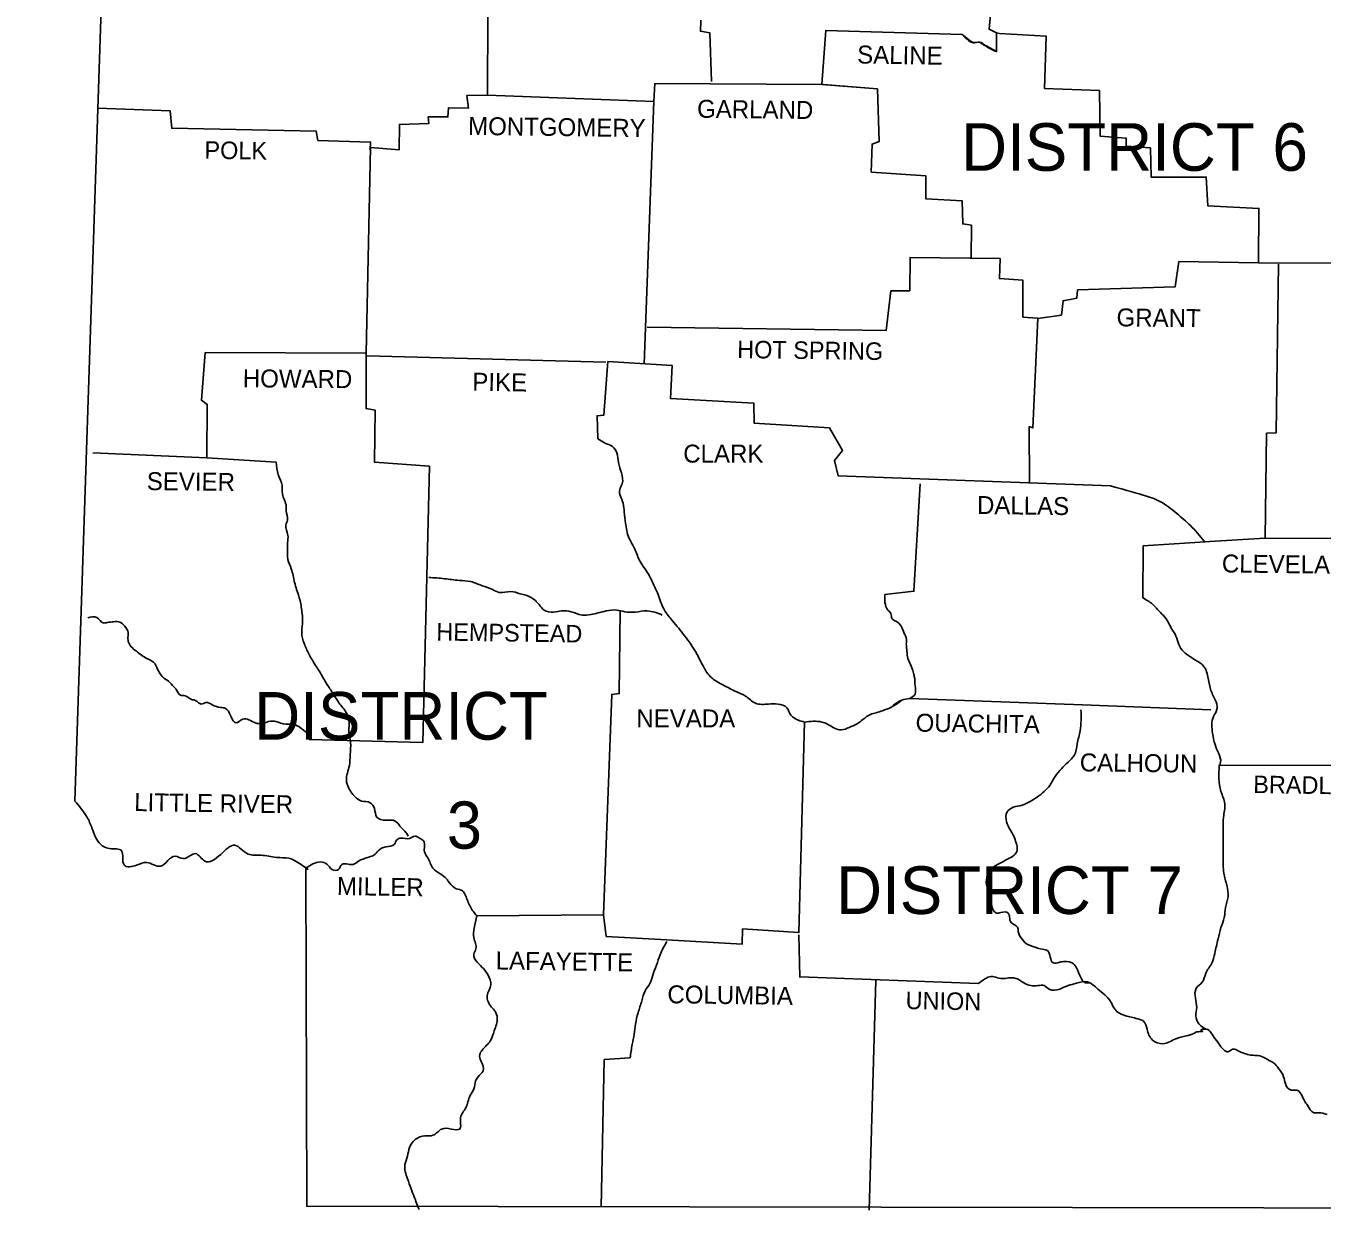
# Model space of a CAD drawing. Extents: x -33639 to 34530, y -17264 to 5867.
# Drawn here: x -17668 to -15961, y 2895 to 4454 of the extents above; entities that cross this region are included whole.
import ezdxf

# ---------------------------------------------------------------- set-up
doc = ezdxf.new("R2010")
doc.units = 0
for name, color, linetype in [('1', 7, 'Continuous'), ('2', 7, 'Continuous'), ('3', 7, 'Continuous'), ('S_MISC_BOUNDARY', 7, 'Continuous')]:
    doc.layers.add(name, color=color, linetype=linetype)

msp = doc.modelspace()

# ---------------------------------------------------------------- linework, layer by layer
at = {"layer": '1'}
for points in [[(-17667.8, 5841.4), (-17553.9, 4926.7), (-17603.4, 3433.6)], [(-17058.6, 4685.1), (-17059.7, 4363.2), (-17087.2, 4362.6), (-17085, 4346.1), (-17111.4, 4346.7), (-17111.9, 4334.6), (-17137.8, 4334.6), (-17137.3, 4325.8), (-17175.8, 4324.7), (-17176.3, 4291.1), (-17213.8, 4294.4), (-17219.8, 4023.6), (-17431.7, 4024.2), (-17436.7, 3961.4), (-17428.9, 3955.9), (-17429.5, 3885.5), (-17579.7, 3892.1)], [(-16215.4, 4527.2), (-16255, 4531.6), (-16253.4, 4516.7), (-16325.5, 4514), (-16327.7, 4492.5), (-16395.4, 4488.7), (-16399.2, 4450.1), (-16389.3, 4445.2), (-16389.3, 4420.6)], [(-16779, 4462.2), (-16779.5, 4447.4), (-16766.9, 4445.2), (-16764.7, 4381.3)], [(-16434.5, 4443), (-16614.4, 4448.5), (-16619.4, 4377.5), (-16839.5, 4378.6), (-16840.6, 4354.9)], [(-16385.5, 4444.6), (-16323.8, 4440.8), (-16326, 4372), (-16253.9, 4369.2), (-16252.8, 4309.2), (-16218.7, 4306.5), (-16218.7, 4296), (-16186.8, 4293.8), (-16185.7, 4255.3), (-16113.1, 4255.3), (-16110.9, 4217.3), (-16043.7, 4214), (-16044.3, 4142.5)], [(-16617.9, 4377.4), (-16546.2, 4371.4), (-16544, 4302.1), (-16553.3, 4298.8), (-16554.4, 4261.9), (-16482.3, 4257), (-16482.3, 4226.7), (-16434.5, 4223.9), (-16433.9, 4193.7), (-16422.4, 4192), (-16422.9, 4148.5)], [(-16840.6, 4354.9), (-17059.7, 4363.2)], [(-16840.6, 4354.9), (-16853.4, 4009.5)], [(-17573.1, 4346.1), (-17477.9, 4342.8), (-17475.7, 4319.7), (-17285.3, 4315.8), (-17283.1, 4303.7), (-17213.8, 4301.5), (-17214.3, 4291.1)], [(-15387.7, 4205.8), (-15595.7, 4211.3), (-15596.8, 4143.6), (-16017.8, 4141.9)], [(-16849.4, 4057.7), (-16534.6, 4053.3), (-16528.6, 4105.6), (-16503.8, 4105.6), (-16503.3, 4149.6), (-16384.4, 4148), (-16385.5, 4121.6), (-16354.7, 4119.4), (-16354.7, 4070.9), (-16336, 4069.4)], [(-16334.8, 4069.3), (-16304, 4073.7), (-16301.8, 4092.4), (-16283.7, 4095.7), (-16282.6, 4106.7), (-16154.3, 4110.6), (-16149.4, 4144.1), (-16017.8, 4141.9)], [(-16017.8, 4140.8), (-16021.1, 3918.5), (-16033.8, 3917.9), (-16035.5, 3779.8)], [(-16334.8, 4069.3), (-16341.4, 3925.1), (-16346.4, 3926.7), (-16345.9, 3851.9)], [(-17219.8, 4023.6), (-17219.8, 3950.4), (-17207.7, 3948.2), (-17208.8, 3880), (-17136.2, 3874.5), (-17145, 3510.7), (-17294.7, 3514.5)], [(-17218.7, 4019.8), (-16903.9, 4011.5)], [(-16914.4, 3910.8), (-16915.5, 3941.1), (-16906.7, 3941.6), (-16901.2, 4012.6), (-16816.4, 4007.1), (-16818.6, 3963.6), (-16709.1, 3957.6), (-16708.5, 3931.2), (-16609.5, 3925.1), (-16592.4, 3895.4), (-16602.9, 3882.2), (-16597.9, 3861.8), (-16239.1, 3848.6)], [(-17429.5, 3885.5), (-17338.1, 3880)], [(-16490, 3851.4), (-16498.3, 3709.9), (-16536.3, 3705.5)], [(-16114.7, 3774.9), (-16196.2, 3769.9), (-16196.7, 3701.1)], [(-16035.5, 3779.8), (-16115.8, 3774.9)], [(-16035.5, 3779.8), (-15840.6, 3778.7)], [(-16885.2, 3684.6), (-16886.3, 3575.1), (-16896.2, 3574), (-16907.2, 3283.9)], [(-16503.8, 3568.5), (-16276, 3560.2), (-16107, 3553.6)], [(-16642.5, 3537.6), (-16649.6, 3260.3), (-16723.9, 3265.2), (-16724.5, 3244.9), (-16823.6, 3250.9)], [(-16096, 3480.4), (-15847.2, 3481)], [(-17299.1, 3345), (-17298, 2899.8), (-15280.9, 2896.5)], [(-16823.6, 3250.9), (-16903.4, 3255.3), (-16907.2, 3283.9), (-17074, 3282.3)], [(-16413.5, 3193.1), (-16648.5, 3201.9), (-16649.6, 3257.5)], [(-16548.4, 3197), (-16557.2, 2894.8)], [(-16872, 3095.2), (-16906.1, 3093), (-16910, 2899.2)]]:
    msp.add_lwpolyline(points, dxfattribs=at)
for points in [[(-16389.3, 4420.6), (-16403.6, 4428.1), (-16411.9, 4433.1), (-16420.7, 4432.5), (-16427.9, 4436.9), (-16434.5, 4443)], [(-16914.4, 3910.8), (-16905.6, 3905.3), (-16895.1, 3900.3), (-16889.6, 3892.1), (-16887.4, 3879.4), (-16883.5, 3865.7), (-16882.4, 3851.4), (-16885.7, 3843.6), (-16881.3, 3826), (-16879.7, 3813.9), (-16878, 3799.6), (-16873.6, 3780.4), (-16866.5, 3767.1), (-16859.9, 3751.2), (-16848.9, 3734.1), (-16839.5, 3715.4), (-16835.1, 3705.5), (-16826.9, 3685.1), (-16816.4, 3671.4), (-16799.9, 3650.5), (-16785, 3629), (-16776.8, 3613), (-16764.1, 3595.4), (-16749.8, 3586.6), (-16731.6, 3577.3), (-16720.1, 3571.8), (-16706.9, 3562.4), (-16689.8, 3561.3), (-16677.2, 3561.3), (-16665.6, 3556.4), (-16660.1, 3546.5), (-16650.2, 3539.9), (-16642.5, 3537.6)], [(-17338.1, 3880), (-17335.4, 3863.5), (-17330.4, 3849.1), (-17329.9, 3838.1), (-17324.9, 3821.6), (-17324.9, 3815.6), (-17323.3, 3803.5), (-17325.5, 3796.9), (-17322.7, 3783.7), (-17323.3, 3773.8), (-17323.3, 3765.5), (-17322.7, 3751.7), (-17318.3, 3739.6), (-17313.9, 3721.5), (-17311.2, 3712.1), (-17306.8, 3697.8), (-17304, 3680.2), (-17303.5, 3667), (-17304.6, 3654.9), (-17301.3, 3641.1), (-17295.2, 3627.4), (-17287.5, 3614.1), (-17278.2, 3599.3), (-17271.5, 3587.7), (-17263.3, 3575.1), (-17256.7, 3564.6), (-17246.8, 3551.4), (-17242.4, 3540.4), (-17242.4, 3525), (-17240.2, 3510.7), (-17240.7, 3494.7), (-17241.8, 3480.4), (-17245.7, 3460.6), (-17242.9, 3451.2), (-17232.5, 3437.5), (-17225.9, 3433.6), (-17214.3, 3431.4), (-17208.8, 3423.7), (-17205.5, 3412.2), (-17193.9, 3408.3), (-17181.3, 3407.2), (-17175.2, 3400.6), (-17167, 3391.8), (-17164.2, 3387.4)], [(-16239.1, 3848.6), (-16196.2, 3836.5), (-16174.1, 3828.2), (-16152.1, 3812.3), (-16134, 3796.3), (-16115.8, 3776)], [(-17137.3, 3728.1), (-17116.3, 3726.4), (-17097.1, 3724.2), (-17082.2, 3722.6), (-17066.8, 3717.1), (-17053.1, 3712.1), (-17044.3, 3708.3), (-17029.4, 3709.4), (-17016.7, 3706.6), (-17002.4, 3701.7), (-16992, 3692.3), (-16985.4, 3685.1), (-16972.7, 3682.4), (-16962.2, 3684), (-16949.6, 3682.9), (-16935.3, 3678.5), (-16923.7, 3679.1), (-16914.4, 3681.3), (-16903.4, 3684), (-16889.6, 3685.1), (-16879.1, 3682.9), (-16865.4, 3682.4), (-16849.4, 3684), (-16829.6, 3678.5)], [(-16536.3, 3705.5), (-16536.3, 3695), (-16532.4, 3685.1), (-16528.6, 3680.7), (-16526.9, 3673.6), (-16522, 3670.3), (-16514.8, 3663.7), (-16511, 3654.3), (-16508.2, 3648.3), (-16508.2, 3640.6), (-16507.7, 3632.9), (-16506.6, 3623.5), (-16500, 3607), (-16498.3, 3600.4), (-16497.2, 3594.9), (-16496.6, 3585.5), (-16496.6, 3574.5), (-16503.8, 3568.5)], [(-16196.7, 3701.1), (-16184, 3692.8), (-16173.6, 3681.8), (-16165.9, 3673.6), (-16160.9, 3664.2), (-16154.3, 3653.2), (-16145, 3632.3), (-16136.7, 3625.2), (-16125.2, 3618), (-16118, 3613), (-16110.9, 3597.1), (-16107.5, 3581.1), (-16101.5, 3566.8), (-16098.7, 3555.8), (-16103.7, 3544.8), (-16104.8, 3522.8), (-16101.5, 3507.9), (-16097.1, 3496.9), (-16094.3, 3484.3), (-16096, 3480.4)], [(-17586.3, 3674.7), (-17574.2, 3675.2), (-17566, 3668.1), (-17561, 3668.6), (-17552.2, 3669.7), (-17544, 3669.2), (-17537.9, 3664.2), (-17533, 3655.4), (-17533.5, 3647.2), (-17533, 3643.9), (-17529.1, 3636.7), (-17522.5, 3631.2), (-17515.4, 3625.7), (-17508.7, 3621.3), (-17497.7, 3614.1), (-17496.6, 3611.9), (-17492.2, 3603.1), (-17486.7, 3596), (-17480.1, 3591.6), (-17473, 3583.9), (-17469.7, 3580.6), (-17464.2, 3572.9), (-17458.1, 3572.3), (-17449.9, 3567.4), (-17443.8, 3565.7), (-17437.2, 3561.3), (-17430.6, 3563.5), (-17422.3, 3560.2), (-17411.3, 3556.9), (-17405.3, 3555.8), (-17398.1, 3545.4), (-17391, 3536.5), (-17382.2, 3541.5), (-17365.7, 3536.5), (-17355.2, 3536), (-17345.8, 3538.7), (-17338.7, 3538.2), (-17325.5, 3534.9), (-17317.2, 3534.9), (-17308.4, 3531.6), (-17300.2, 3525), (-17294.7, 3517.8), (-17294.7, 3514.5)], [(-16528.6, 3556.9), (-16514.3, 3566.3), (-16503.8, 3568.5)], [(-16514.3, 3566.3), (-16528.6, 3556.9), (-16539.6, 3552.5), (-16547.8, 3549.8), (-16555.5, 3547.6), (-16565.4, 3541), (-16573.1, 3535.4), (-16583.6, 3530.5), (-16593.5, 3527.2), (-16605.6, 3531), (-16612.2, 3534.9), (-16619.4, 3537.6), (-16642.5, 3537.6)], [(-16278.2, 3553.6), (-16279.3, 3526.1), (-16283.1, 3509), (-16287, 3493.6), (-16295.2, 3484.8), (-16304, 3476), (-16312.3, 3466.1), (-16319.4, 3454), (-16326.6, 3446.3), (-16335.9, 3438.6), (-16345.3, 3433.1), (-16355.8, 3428.1), (-16367.3, 3425.4), (-16375.6, 3419.3), (-16376.1, 3406.1), (-16366.8, 3387.4), (-16363.5, 3378.6), (-16362.4, 3368.1), (-16366.2, 3362.1), (-16375, 3357.1), (-16385.5, 3351.1), (-16394.8, 3345.6), (-16401.4, 3336.2), (-16402.5, 3323.6), (-16398.1, 3308.7), (-16396.5, 3299.9), (-16389.3, 3286.1), (-16383.8, 3286.7), (-16373.9, 3286.1), (-16372.8, 3283.4), (-16372.3, 3280.6), (-16370.1, 3273.5), (-16361.8, 3267.4), (-16360.7, 3261.9), (-16355.8, 3251.5), (-16347.5, 3244.3), (-16341.4, 3242.1), (-16328.8, 3238.3), (-16322.2, 3236.6), (-16315, 3220.6), (-16306.2, 3221.2), (-16299.6, 3222.3), (-16288.6, 3219.5), (-16283.7, 3212.9), (-16278.7, 3201.9), (-16272.1, 3194.2), (-16267.7, 3194.2)], [(-16096, 3480.4), (-16093.8, 3446.3), (-16088.8, 3429.8), (-16090.5, 3412.2), (-16091, 3395.1), (-16091, 3379.7), (-16091, 3364.8), (-16091, 3349.4), (-16089.9, 3338.4), (-16086.1, 3322.5), (-16084.4, 3307.6), (-16087.7, 3293.3), (-16089.4, 3280.1), (-16093.8, 3266.9), (-16097.6, 3252), (-16102, 3232.8), (-16105.9, 3220.1), (-16113.6, 3206.9), (-16118.6, 3194.8), (-16126.3, 3187.1), (-16127.4, 3173.9), (-16125.7, 3161.8), (-16126.8, 3150.7), (-16123, 3140.3), (-16113.1, 3133.1)], [(-17603.4, 3433.6), (-17587.5, 3412.7), (-17580.8, 3397.9), (-17571.5, 3378.6), (-17557.7, 3370.9), (-17541.8, 3368.1), (-17538.5, 3349.4), (-17522, 3348.9), (-17508.7, 3352.7), (-17490.6, 3347.8), (-17471.3, 3361), (-17460.3, 3357.7), (-17444.4, 3364.3), (-17432.3, 3354.4), (-17411.3, 3363.2), (-17392.6, 3375.3), (-17375, 3363.7), (-17358, 3362.1), (-17337.6, 3359.3), (-17321.6, 3358.2), (-17307.3, 3351.1), (-17296.9, 3343.9), (-17299.1, 3345)], [(-17299.1, 3345), (-17279.8, 3353.3), (-17271.5, 3350.5), (-17264.4, 3343.4), (-17256.1, 3343.4), (-17251.7, 3350), (-17243.5, 3350.5), (-17236.9, 3350), (-17229.7, 3354.4), (-17223.7, 3357.1), (-17215.4, 3359.9), (-17209.4, 3362.1), (-17203.9, 3368.1), (-17193.9, 3373.1), (-17182.4, 3376.9), (-17179.1, 3382.4), (-17173.6, 3384.7), (-17162.6, 3384.1), (-17155.4, 3387.4), (-17149.4, 3384.7), (-17143.9, 3380.8), (-17142.8, 3366.5), (-17138.4, 3358.8), (-17131.8, 3345), (-17122.4, 3337.9), (-17113.6, 3330.7), (-17110.3, 3326.3), (-17100.9, 3318.1), (-17092.7, 3315.3), (-17088.8, 3309.3), (-17082.8, 3294.9), (-17074, 3282.3)], [(-17074, 3282.3), (-17077.3, 3266.3), (-17077.8, 3253.7), (-17075.1, 3238.8), (-17077.8, 3231.7), (-17073.4, 3221.2), (-17065.2, 3212.9), (-17059.1, 3204.1), (-17055.3, 3191.5), (-17060.2, 3177.2), (-17054.7, 3162.3), (-17049.8, 3156.8), (-17047, 3148), (-17050.9, 3130.9), (-17055.8, 3118.3), (-17066.8, 3105.6), (-17070.1, 3099.6), (-17068.5, 3091.3), (-17065.7, 3078.1), (-17068.5, 3074.3), (-17075.6, 3064.9), (-17077.8, 3054.4), (-17082.8, 3045.6), (-17088.3, 3029.7), (-17095.4, 3016.5), (-17096.5, 3001.6), (-17107.5, 3001.6), (-17120.2, 3001.6), (-17131.8, 2993.3), (-17142.2, 2992.8), (-17154.9, 2987.8), (-17162.6, 2977.4), (-17165.3, 2965.8), (-17168.6, 2954.8), (-17165.3, 2936.1), (-17160.4, 2922.9), (-17156.5, 2912.4), (-17149.9, 2895.4)], [(-16872, 3095.2), (-16869.2, 3112.8), (-16866.5, 3126.5), (-16864.8, 3139.7), (-16861.5, 3154.6), (-16856.6, 3170.6), (-16852.2, 3183.8), (-16846.1, 3193.1), (-16842.3, 3204.1), (-16837.3, 3217.3), (-16832.4, 3231.1), (-16823.6, 3248.7)], [(-16413.5, 3193.1), (-16404.7, 3199.2), (-16396.5, 3202.5), (-16388.2, 3200.8), (-16379.4, 3199.7), (-16371.7, 3200.8), (-16361.8, 3199.2), (-16353.6, 3194.2), (-16344.2, 3190.4), (-16334.8, 3190.4), (-16326.6, 3190.4), (-16319.4, 3185.4), (-16306.2, 3186), (-16295.2, 3190.4), (-16284.2, 3193.7), (-16269.4, 3195.3), (-16256.1, 3186), (-16246.8, 3178.3), (-16239.1, 3169.5), (-16233.6, 3159.6), (-16227.5, 3154.1), (-16217.6, 3150.2), (-16209.9, 3148.5), (-16200.6, 3145.8), (-16195.6, 3143.6), (-16191.2, 3133.1), (-16184, 3118.8), (-16170.3, 3113.9), (-16153.2, 3120.5), (-16139.5, 3124.3), (-16129.6, 3127.6), (-16123.5, 3129.8), (-16118, 3130.4), (-16119.7, 3131.5), (-16113.1, 3133.1), (-16107, 3128.7), (-16103.1, 3122.7), (-16096.5, 3113.9), (-16090.5, 3106.2), (-16084.4, 3103.4), (-16078.4, 3106.7), (-16070.1, 3104), (-16063, 3101.2), (-16054.7, 3099), (-16047.6, 3098.5), (-16038.2, 3096.3), (-16031, 3092.4), (-16024.4, 3088.6), (-16017.8, 3081.4), (-16011.2, 3070.4), (-16009, 3061.6), (-16001.3, 3052.8), (-15994.2, 3052.8), (-15983.7, 3038.5), (-15979.9, 3033), (-15971.6, 3023.1), (-15965.6, 3023.1), (-15954, 3020.9)]]:
    msp.add_spline(points, degree=3, dxfattribs=at)
at = {"layer": 'S_MISC_BOUNDARY'}
for p, q in [((-16614.4, 4448.5), (-16619.4, 4377.5)), ((-16434.5, 4443), (-16614.4, 4448.5)), ((-16389.3, 4445.2), (-16389.3, 4420.6)), ((-16326, 4372), (-16323.8, 4440.8)), ((-16389.3, 4420.6), (-16394.3, 4423.4)), ((-16619.4, 4377.5), (-16617.9, 4377.4)), ((-16617.9, 4377.4), (-16546.2, 4371.4)), ((-16253.9, 4369.2), (-16326, 4372)), ((-16186.8, 4293.8), (-16218.7, 4296)), ((-16482.3, 4226.7), (-16434.5, 4223.9)), ((-16434.5, 4223.9), (-16433.9, 4193.7)), ((-16304, 4073.7), (-16301.8, 4092.4)), ((-16301.8, 4092.4), (-16283.7, 4095.7)), ((-16354.7, 4070.9), (-16336, 4069.4)), ((-16336, 4069.4), (-16334.8, 4069.3)), ((-16334.8, 4069.3), (-16304, 4073.7))]:
    msp.add_line(p, q, dxfattribs=at)
for points in [[(-16619.4, 4377.5), (-16614.4, 4448.5), (-16434.5, 4443), (-16424.3, 4434.7), (-16420.7, 4432.5), (-16416.3, 4432.8), (-16411.9, 4433.1), (-16389.3, 4420.6), (-16389.3, 4445.2), (-16385.5, 4444.6), (-16323.8, 4440.8), (-16326, 4372), (-16253.9, 4369.2), (-16253.4, 4339.2), (-16252.8, 4309.2), (-16218.6, 4306.5), (-16218.8, 4296), (-16186.7, 4293.8), (-16185.7, 4255.3), (-16113.1, 4255.3), (-16110.9, 4217.3), (-16043.7, 4214), (-16044.3, 4142.5), (-16149.4, 4144.1), (-16154.3, 4110.6), (-16282.6, 4106.7), (-16283.7, 4095.7), (-16301.8, 4092.4), (-16304, 4073.7), (-16334.8, 4069.3), (-16336, 4069.4), (-16354.7, 4070.9), (-16354.7, 4119.4), (-16385.5, 4121.6), (-16384.4, 4148), (-16422.9, 4148.5), (-16422.4, 4192), (-16433.9, 4193.7), (-16434.5, 4223.9), (-16482.3, 4226.7), (-16482.3, 4257), (-16554.4, 4261.9), (-16553.3, 4298.8), (-16544, 4302.1), (-16546.2, 4371.4), (-16619.4, 4377.5)], [(-16323.8, 4440.8), (-16385.5, 4444.6), (-16389.3, 4445.2)], [(-16411, 4432.6), (-16411.9, 4433.1), (-16416.3, 4432.8), (-16416.6, 4432.8)], [(-16546.2, 4371.4), (-16544, 4302.1), (-16553.3, 4298.8), (-16554.4, 4261.9)], [(-16218.7, 4296), (-16218.7, 4306.5), (-16252.8, 4309.2), (-16253.4, 4339.2), (-16253.9, 4369.2)], [(-16113.1, 4255.3), (-16185.7, 4255.3), (-16186.8, 4293.8)], [(-16554.4, 4261.9), (-16482.3, 4257), (-16482.3, 4226.7)], [(-16283.7, 4095.7), (-16282.6, 4106.7), (-16154.3, 4110.6), (-16149.4, 4144.1), (-16044.3, 4142.5), (-16043.7, 4214), (-16110.9, 4217.3), (-16113.1, 4255.3)], [(-16433.9, 4193.7), (-16422.4, 4192), (-16422.9, 4148.5)], [(-16422.9, 4148.5), (-16384.4, 4148), (-16385.5, 4121.6)], [(-16385.5, 4121.6), (-16354.7, 4119.4), (-16354.7, 4070.9)]]:
    msp.add_lwpolyline(points, dxfattribs=at)
msp.add_open_spline([(-16416.6, 4432.8), (-16418, 4432.4), (-16419.4, 4432), (-16420.7, 4432.5), (-16423.3, 4433.6), (-16425.7, 4435.1), (-16427.9, 4436.9), (-16430.2, 4438.9), (-16432.4, 4440.8), (-16434.5, 4443)], degree=3, dxfattribs=at)
msp.add_spline([(-16394.3, 4423.4), (-16399, 4425.7), (-16403.6, 4428.1), (-16404.6, 4428.6), (-16405.5, 4429.2), (-16407.3, 4430.3), (-16409.1, 4431.5), (-16411, 4432.6)], degree=3, dxfattribs=at)

# ---------------------------------------------------------------- texts
at = {"layer": '2'}
for s, height, rotation, p in [('SALINE', 23.67, 359.1491, (-16573.1, 4405)), ('GARLAND', 23.67, 359.3658, (-16783.9, 4333.5)), ('MONTGOMERY', 23.67, 359.2944, (-17085.5, 4310.9)), ('POLK', 23.11, 359.2152, (-17432.8, 4279.5)), ('GRANT', 23.67, 359.4032, (-16231.4, 4058.8)), ('HOT SPRING', 23.11, 359.2216, (-16731.1, 4017)), ('HOWARD', 23.67, 359.5145, (-17382.2, 3978.5)), ('PIKE', 23.66, 359.0452, (-17080, 3974.1)), ('SEVIER', 23.67, 359.4271, (-17508.7, 3843.1)), ('DALLAS', 23.66, 359.2462, (-16415.2, 3811.7)), ('CLEVELAND', 23.67, 359.3377, (-16092.7, 3734.7)), ('HEMPSTEAD', 23.11, 359.1885, (-17127.4, 3645)), ('OUACHITA', 23.67, 359.2043, (-16496.1, 3525)), ('CALHOUN', 23.67, 359.3634, (-16279.8, 3472.7)), ('BRADLEY', 23.11, 359.1449, (-16051.4, 3444.1)), ('LITTLE RIVER', 23.666, 359.1697, (-17525.3, 3420.4)), ('MILLER', 23.66, 359.1319, (-17258.3, 3309.8)), ('LAFAYETTE', 23.66, 359.1839, (-17049.2, 3211.8)), ('COLUMBIA', 23.66, 359.2125, (-16823, 3167.3)), ('UNION', 23.11, 358.9584, (-16509.3, 3159.6))]:
    msp.add_text(s, height=height, rotation=rotation, dxfattribs=at).set_placement(p)
for s, p in [('CLARK', (-16802, 3879.3)), ('NEVADA', (-16863.7, 3530.5))]:
    msp.add_text(s, height=23.67, dxfattribs=at).set_placement(p)
at = {"layer": '3'}
for s, height, p in [('DISTRICT 6', 62.74, (-16436.1, 4263.6)), ('DISTRICT', 62.74, (-17367.1, 3514.4)), ('3', 62.2, (-17113.4, 3370.8)), ('DISTRICT 7', 62.74, (-16600.8, 3284.8))]:
    msp.add_text(s, height=height, dxfattribs=at).set_placement(p)

doc.saveas('drawing.dxf')
